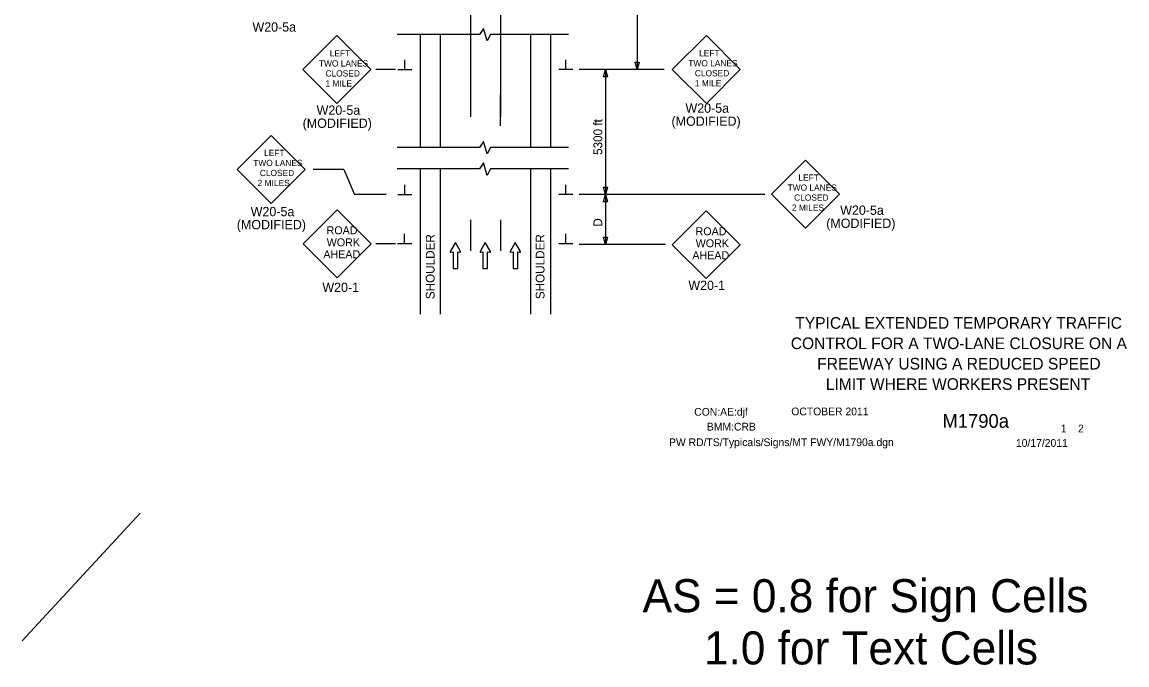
# Model space of a CAD drawing. Extents: x 16553 to 18475, y 5759 to 7026.
# Drawn here: x 16553 to 17437, y 5759 to 6273 of the extents above; entities that cross this region are included whole.
import ezdxf

# ---------------------------------------------------------------- set-up
doc = ezdxf.new("R2010")
doc.units = 0
for name, color, linetype in [('ALI_LEGAL_EX', 7, 'Continuous'), ('BORDER', 7, 'Continuous'), ('BORDER_SIGNAL_WO', 7, 'Continuous'), ('MT_SCRATCH_LEVEL_E', 7, 'Continuous'), ('PAVT_EDGE_EX', 7, 'Continuous'), ('TRAFFIC_SIGNS_PR', 7, 'Continuous'), ('TYPICAL_TEXT_DIMEN_PR', 7, 'Continuous')]:
    doc.layers.add(name, color=color, linetype=linetype)

msp = doc.modelspace()

# ---------------------------------------------------------------- linework, layer by layer
at = {"layer": 'ALI_LEGAL_EX'}
for p, q in [((16911.66, 7026.35), (16911.66, 6197.16)), ((16935.66, 7026.35), (16935.66, 6197.16)), ((16935.66, 7026.35), (16935.66, 6197.16))]:
    msp.add_line(p, q, dxfattribs=at)
for points in [[(16911.66, 6252.16), (16911.66, 6227.16)], [(16935.66, 6252.16), (16935.66, 6227.16)], [(16935.66, 6189.81), (16935.66, 6214.81)], [(16911.66, 6114.81), (16911.66, 6089.81)], [(16935.66, 6114.81), (16935.66, 6089.81)]]:
    msp.add_lwpolyline(points, dxfattribs=at)
at = {"layer": 'MT_SCRATCH_LEVEL_E'}
for p, q in [((16899.66, 6096.71), (16895.55, 6089.47)), ((16903.81, 6089.47), (16899.66, 6096.71)), ((16923.57, 6096.71), (16919.46, 6089.47)), ((16927.71, 6089.47), (16923.57, 6096.71)), ((16947.62, 6096.71), (16943.51, 6089.47)), ((16951.77, 6089.47), (16947.62, 6096.71)), ((16896.03, 6088.78), (16897.81, 6089.1)), ((16897.81, 6089.1), (16897.81, 6075.84)), ((16901.55, 6075.84), (16901.55, 6089.1)), ((16901.55, 6089.1), (16903.33, 6088.78)), ((16919.94, 6088.78), (16921.72, 6089.1)), ((16921.72, 6089.1), (16921.72, 6075.84)), ((16925.46, 6075.84), (16925.46, 6089.1)), ((16925.46, 6089.1), (16927.24, 6088.78)), ((16943.99, 6088.78), (16945.77, 6089.1)), ((16945.77, 6089.1), (16945.77, 6075.84)), ((16949.51, 6075.84), (16949.51, 6089.1)), ((16949.51, 6089.1), (16951.29, 6088.78)), ((16897.81, 6075.84), (16901.55, 6075.84)), ((16921.72, 6075.84), (16925.46, 6075.84)), ((16945.77, 6075.84), (16949.51, 6075.84))]:
    msp.add_line(p, q, dxfattribs=at)
for centre, start, end in [((16895.96, 6089.24), 150.42484, 279.96381), ((16903.4, 6089.24), 260.03619, 29.77312), ((16919.86, 6089.24), 150.42484, 279.96381), ((16927.3, 6089.24), 260.03619, 29.77312), ((16943.92, 6089.24), 150.42484, 279.96381), ((16951.36, 6089.24), 260.03619, 29.77312)]:
    msp.add_arc(centre, 0.463, start, end, dxfattribs=at)
at = {"layer": 'PAVT_EDGE_EX'}
for p, q in [((16871.66, 6263.07), (16871.66, 6172.6)), ((16887.66, 6263.07), (16887.66, 6172.61)), ((16959.66, 6263.07), (16959.66, 6172.61)), ((16975.66, 6263.07), (16975.66, 6172.61)), ((16959.66, 6252.6), (16959.66, 6249.77)), ((16871.66, 6155.48), (16871.66, 6039.39)), ((16887.66, 6155.48), (16887.66, 6039.39)), ((16959.66, 6155.46), (16959.66, 6039.39)), ((16975.66, 6155.46), (16975.66, 6039.39))]:
    msp.add_line(p, q, dxfattribs=at)
at = {"layer": 'TRAFFIC_SIGNS_PR'}
for p, q in [((16804.98, 6262.11), (16777.79, 6234.92)), ((16832.16, 6234.92), (16804.98, 6262.11)), ((17100.37, 6262.23), (17073.18, 6235.04)), ((17127.55, 6235.04), (17100.37, 6262.23)), ((16777.79, 6234.92), (16804.98, 6207.73)), ((16804.98, 6207.73), (16832.16, 6234.92)), ((17073.18, 6235.04), (17100.37, 6207.85)), ((17100.37, 6207.85), (17127.55, 6235.04)), ((16752.46, 6182.13), (16725.27, 6154.95)), ((16779.65, 6154.95), (16752.46, 6182.13)), ((17179.74, 6162.4), (17152.55, 6135.22)), ((17206.92, 6135.22), (17179.74, 6162.4)), ((16725.27, 6154.95), (16752.46, 6127.76)), ((16752.46, 6127.76), (16779.65, 6154.95)), ((17152.55, 6135.22), (17179.74, 6108.03)), ((17179.74, 6108.03), (17206.92, 6135.22)), ((16805.16, 6122.77), (16778.01, 6095.62)), ((16832.32, 6095.62), (16805.16, 6122.77)), ((17100.21, 6122), (17073.06, 6094.84)), ((17127.36, 6094.84), (17100.21, 6122)), ((16778.01, 6095.62), (16805.16, 6068.47)), ((16805.16, 6068.47), (16832.32, 6095.62)), ((17073.06, 6094.84), (17100.21, 6067.69)), ((17100.21, 6067.69), (17127.36, 6094.84))]:
    msp.add_line(p, q, dxfattribs=at)
at = {"layer": 'TYPICAL_TEXT_DIMEN_PR'}
for p, q in [((17045.1, 6510.5), (17045.1, 6235.04)), ((16922.27, 6267.87), (16919.01, 6263.07)), ((16925.01, 6257.93), (16922.27, 6267.87)), ((16919.01, 6263.07), (16853.07, 6263.07)), ((16927.75, 6263.07), (16925.01, 6257.93)), ((16990.08, 6263.07), (16927.75, 6263.07)), ((16859.29, 6235.04), (16859.29, 6242.82)), ((16988.04, 6235.04), (16988.04, 6242.82)), ((17045.1, 6235.04), (17043.53, 6240.9)), ((17043.53, 6240.9), (17045.1, 6240.9)), ((17045.1, 6240.9), (17046.67, 6240.9)), ((17046.67, 6240.9), (17045.1, 6235.04)), ((16851.75, 6235.04), (16836.16, 6235.04)), ((16853.66, 6235.04), (16864.91, 6235.04)), ((16993.66, 6235.04), (16982.41, 6235.04)), ((17066.7, 6235.04), (16998.66, 6235.04)), ((17018.09, 6229.18), (17019.66, 6235.04)), ((17019.66, 6229.18), (17018.09, 6229.18)), ((17019.66, 6235.04), (17019.66, 6135.04)), ((17019.66, 6235.04), (17021.24, 6229.18)), ((17021.24, 6229.18), (17019.66, 6229.18)), ((16922.27, 6177.4), (16919.01, 6172.6)), ((16925.01, 6167.46), (16922.27, 6177.4)), ((16919.01, 6172.6), (16853.07, 6172.6)), ((16927.75, 6172.6), (16925.01, 6167.46)), ((16990.08, 6172.6), (16927.75, 6172.6)), ((16922.27, 6160.26), (16919.01, 6155.46)), ((16925.01, 6150.32), (16922.27, 6160.26)), ((16810.37, 6154.94), (16785.84, 6154.94)), ((16810.37, 6154.94), (16819.13, 6135.04)), ((16919.01, 6155.46), (16853.07, 6155.46)), ((16927.75, 6155.46), (16925.01, 6150.32)), ((16990.08, 6155.46), (16927.75, 6155.46)), ((16859.29, 6135.04), (16859.29, 6142.82)), ((16988.04, 6135.04), (16988.04, 6142.82)), ((17019.66, 6135.04), (17018.09, 6140.9)), ((17018.09, 6140.9), (17019.66, 6140.9)), ((17019.66, 6140.9), (17021.24, 6140.9)), ((17021.24, 6140.9), (17019.66, 6135.04)), ((16844.35, 6135.04), (16819.13, 6135.04)), ((16853.66, 6135.04), (16864.91, 6135.04)), ((16993.66, 6135.04), (16982.41, 6135.04)), ((17147.25, 6135.04), (16998.66, 6135.04)), ((17018.09, 6129.18), (17019.66, 6135.04)), ((17019.66, 6135.04), (17019.66, 6095.04)), ((17019.66, 6135.04), (17021.24, 6129.18)), ((17019.66, 6129.18), (17018.09, 6129.18)), ((17021.24, 6129.18), (17019.66, 6129.18)), ((16859.13, 6095.66), (16859.13, 6103.44)), ((16988.04, 6095.66), (16988.04, 6103.44)), ((17019.66, 6095.04), (17018.09, 6100.9)), ((17018.09, 6100.9), (17019.66, 6100.9)), ((17019.66, 6100.9), (17021.24, 6100.9)), ((17021.24, 6100.9), (17019.66, 6095.04)), ((16851.75, 6095.66), (16836.16, 6095.66)), ((16864.75, 6095.66), (16853.5, 6095.66)), ((16993.66, 6095.66), (16982.41, 6095.66)), ((17067.78, 6095.04), (16998.66, 6095.04)), ((16647.75, 5880), (16553.21, 5777.94))]:
    msp.add_line(p, q, dxfattribs=at)

# ---------------------------------------------------------------- texts
at = {"layer": 'BORDER'}
for s, p in [('TYPICAL EXTENDED TEMPORARY TRAFFIC', (17171.54, 6027.6)), ('CONTROL FOR A TWO-LANE CLOSURE ON A', (17167.92, 6011.3)), ('FREEWAY USING A REDUCED SPEED', (17189.02, 5995)), ('LIMIT WHERE WORKERS PRESENT', (17195.92, 5978.7))]:
    msp.add_text(s, height=9.3, dxfattribs=at).set_placement(p)
at = {"layer": 'BORDER_SIGNAL_WO'}
for s, height, p in [('CON:AE:djf  ', 6.2, (17090.69, 5958.06)), ('    OCTOBER 2011', 6.2, (17159.08, 5958.34)), ('    M1790a   ', 11, (17272.86, 5948.38)), ('BMM:CRB', 6.2, (17100.81, 5946.17)), (' 1    2 ', 6.2, (17381.45, 5944.7)), ('PW RD/TS/Typicals/Signs/MT FWY/M1790a.dgn      ', 6.2, (17070.55, 5933.71)), ('10/17/2011', 6.2, (17347.93, 5933.13)), ('AS = 0.8 for Sign Cells', 26.4241, (17049.39, 5800.83)), ('     1.0 for Text Cells', 26.4241, (17049.39, 5759.05))]:
    msp.add_text(s, height=height, dxfattribs=at).set_placement(p)
at = {"layer": 'TRAFFIC_SIGNS_PR'}
for s, height, p in [('W20-5a', 7.44, (16737.44, 6265.3)), ('LEFT', 5.006, (16799.22, 6245.41)), ('LEFT', 5.006, (17094.61, 6245.53)), ('TWO LANES', 5.006, (16790.57, 6237.4)), ('TWO LANES', 5.006, (17085.96, 6237.52)), ('CLOSED', 5.006, (16795.8, 6229.4)), ('CLOSED', 5.006, (17091.19, 6229.52)), ('1 MILE', 5.006, (16795.79, 6221.39)), ('1 MILE', 5.006, (17091.19, 6221.51)), ('W20-5a', 7.449, (16788.73, 6198.77)), ('W20-5a', 7.449, (17083.69, 6200.4)), ('(MODIFIED)', 7.449, (16777.57, 6188.32)), ('(MODIFIED)', 7.449, (17072.53, 6189.95)), ('LEFT', 5.006, (16746.7, 6165.74)), ('TWO LANES', 5.006, (16738.05, 6157.73)), ('CLOSED', 5.006, (16743.28, 6149.72)), ('LEFT', 5.006, (17173.98, 6146.01)), ('2 MILES', 5.006, (16741.53, 6141.72)), ('TWO LANES', 5.006, (17165.33, 6138.01)), ('CLOSED', 5.006, (17170.56, 6130)), ('W20-5a', 7.449, (16736.04, 6117.64)), ('2 MILES', 5.006, (17168.81, 6121.99)), ('W20-5a', 7.449, (17207.42, 6118.74)), ('(MODIFIED)', 7.449, (16724.88, 6107.19)), ('(MODIFIED)', 7.449, (17196.26, 6108.29)), ('ROAD', 6.4, (16796.7, 6103.16)), ('ROAD', 6.4, (17091.75, 6102.38)), ('WORK', 6.4, (16796.81, 6093.56)), ('WORK', 6.4, (17091.86, 6092.78)), ('AHEAD', 6.4, (16794.12, 6083.96)), ('AHEAD', 6.4, (17089.17, 6083.18)), ('W20-1', 7.44, (16793.33, 6057.03)), ('W20-1', 7.44, (17086.02, 6058.61))]:
    msp.add_text(s, height=height, dxfattribs=at).set_placement(p)
at = {"layer": 'TYPICAL_TEXT_DIMEN_PR'}
for s, p in [('5300 ft', (17017.11, 6166.65)), ('D', (17017.11, 6109.26)), ('SHOULDER', (16883.08, 6051.25)), ('SHOULDER', (16970.94, 6051.25))]:
    msp.add_text(s, height=7, rotation=90, dxfattribs=at).set_placement(p)

doc.saveas('drawing.dxf')
